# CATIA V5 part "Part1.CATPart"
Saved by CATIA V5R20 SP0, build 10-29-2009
Part number: Part1
Bounding box of the stored display mesh (mm): x -50 to 50, y -50 to 50, z 0 to 120
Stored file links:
  C:\Users\YS\Desktop\독수리\Part1.CATPart
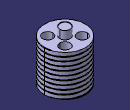
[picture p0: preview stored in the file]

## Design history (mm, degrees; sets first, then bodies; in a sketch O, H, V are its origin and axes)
Body1 (main body)
  Sketch1 on xy-plane, origin (0, 0, 0), H (1, 0, 0), V (0, 1, 0)
    circle A1 centre (0, 0) radius 50
    radius A1 = 50
  Pad1: profile Sketch1, direction (0, 0, 1), length 100
  Sketch2 on end face of Pad1, origin (0, 0, 100), H (1, 0, 0), V (0, 1, 0)
    circle A1 centre (0, 0) radius 12.5
    radius A1 = 12.5
  Pad2: profile Sketch2, direction (0, 0, 1), length 20
  Sketch3 on end face of Pad1, origin (0, 0, 100), H (1, 0, 0), V (0, 1, 0)
    point P1 (21.2132, 21.2132)
    axis line L1 (0, 0) -> (21.2132, 21.2132)
    point P2 (21.2132, 21.2132)
    circle A1 centre (21.2132, -21.2132) radius 12.5
    angle L1 H = 45
    length L1 = 30
    coincidence: P1 L1, P1 P2
  Pocket1: profile Sketch3, direction (0, 0, -1), through (limit type 3)
  Sketch4 on start face of Pad1, origin (0, 0, 0), H (1, 0, 0), V (0, -1, 0)
    circle A1 centre (42.5, 0) radius 2.5
    point P1 (42.5, 0)
    circle A2 centre (-42.5, 0) radius 2.5
    axis line L1 (0, 0) -> (41.0138, 41.0138)
    circle A3 centre (0, 42.5) radius 2.5
    circle A4 centre (0, -42.5) radius 2.5
    radius A1 = 2.5
    distance P1 V = 42.5
    angle L1 H = 45
    coincidence: P1 H
    symmetry: A1 A2 V, A1 A3 L1, A3 A4 H
  CircPattern1: of Pocket1, instances 4, angular step 90, axis from start face of Pad1
  Pocket2: profile Sketch4, direction (0, 0, 1), length 20
  Helix1: Direction Z axis, RefPoint {point type OnCurve, Support edge [start face of Pad1 | face of Pad1 from Sketch1.A1], RefPoint {extremum Reference edge [start face of Pad1 | face of Pad1 from Sketch1.A1], Direction (1, 2, 3)}, Length 270.673}, Pitch 10, Height 100, TaperAngle 0
  Plane1: type Normal, Curve Helix1, RefPoint vertex of Helix1
  Sketch5 on Plane1, origin (0, 0, 0), H (-0.9719, -0.2352, 0), V (0.0075, -0.0309, 0.9995)
    circle A1 centre (-50, 0) radius 1
    point P1 (-50, 0)
    reference projected point E1 (-50, 0) from vertex of Helix1
    radius A1 = 1
    coincidence: P1 E1
  Slot1: profile Sketch5, centre curve Helix1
